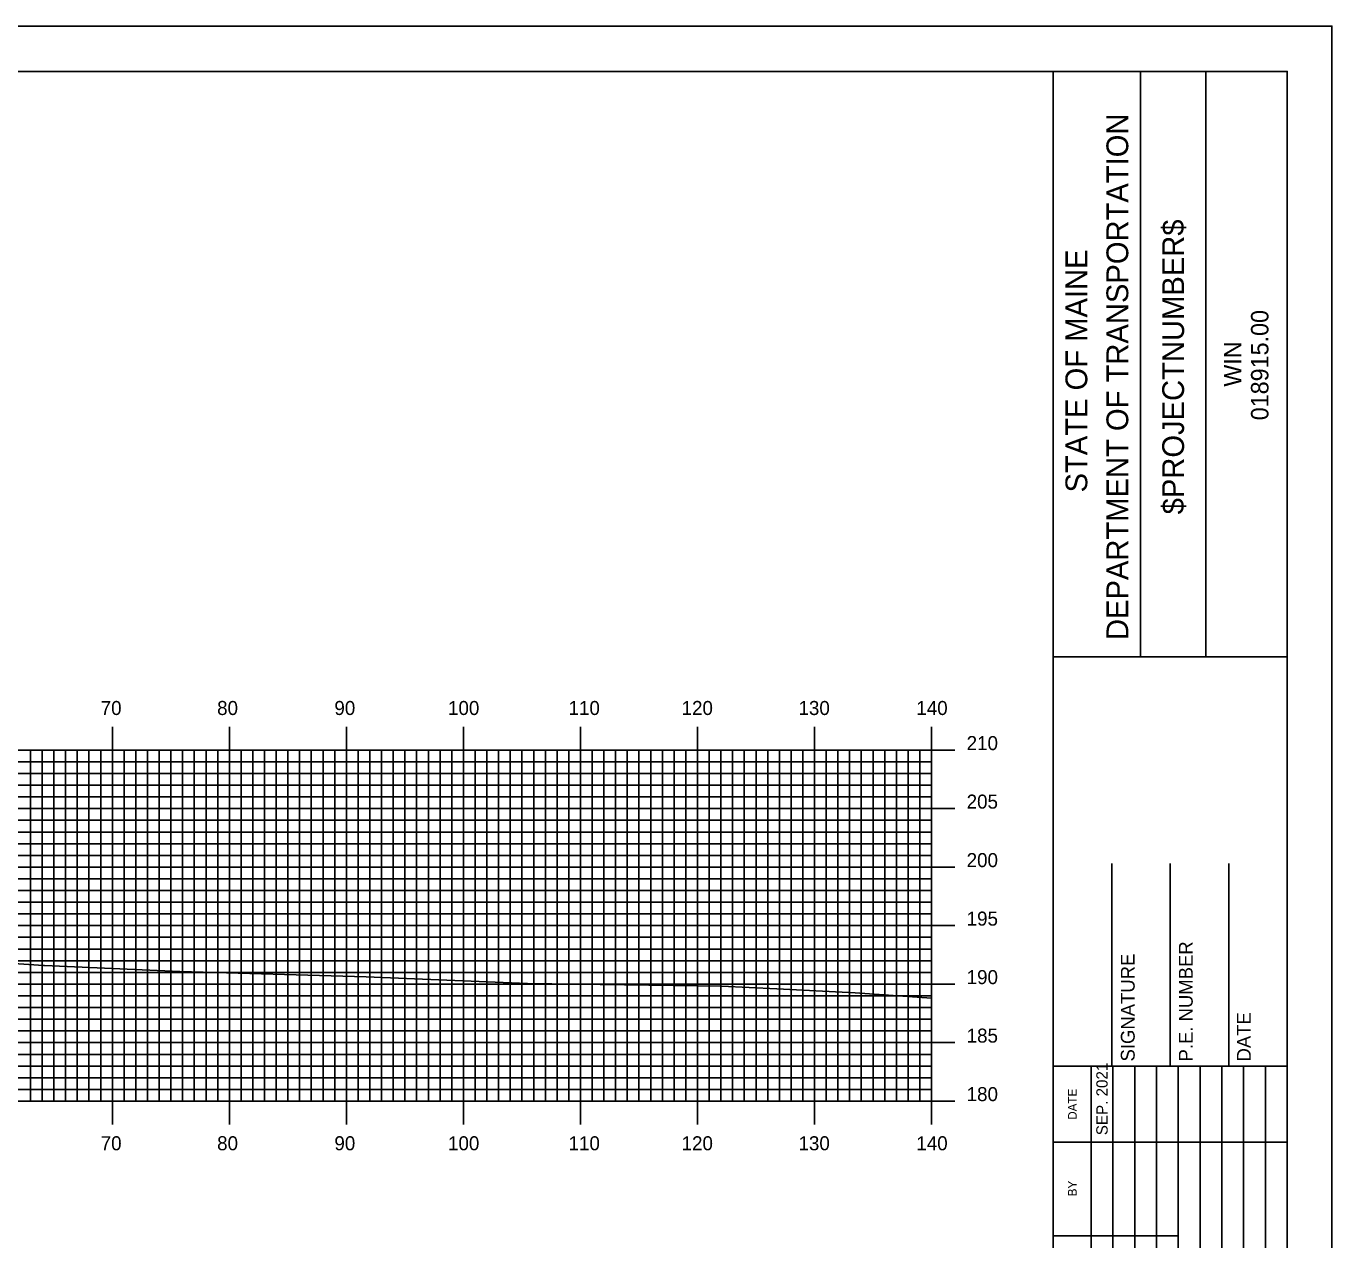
# Model space of a CAD drawing. Extents: x 1807045 to 1807388, y 442591 to 442811.
# Drawn here: x 1807273.4 to 1807385, y 442706.8 to 442810.5 of the extents above; entities that cross this region are included whole.
import ezdxf

# ---------------------------------------------------------------- set-up
doc = ezdxf.new("R2010")
doc.units = 0
for name, color, linetype in [('BORDER', 7, 'Continuous'), ('H_V ANNOTATION', 7, 'Continuous'), ('MAJOR', 7, 'Continuous'), ('MINOR', 7, 'Continuous'), ('PLOT BOUNDARY', 7, 'Continuous'), ('S_Roadway_Centerline', 7, 'Continuous')]:
    doc.layers.add(name, color=color, linetype=linetype)

msp = doc.modelspace()

# ---------------------------------------------------------------- linework, layer by layer
at = {"layer": 'BORDER'}
for p, q in [((1807361.16, 442596.67), (1807361.16, 442806.67)), ((1807368.62, 442756.66), (1807368.62, 442806.66)), ((1807374.21, 442756.66), (1807374.21, 442806.66)), ((1807361.16, 442756.65), (1807381.16, 442756.65)), ((1807366.16, 442721.67), (1807366.16, 442738.97)), ((1807371.16, 442721.67), (1807371.16, 442738.97)), ((1807376.16, 442721.67), (1807376.16, 442738.97)), ((1807361.16, 442721.67), (1807381.16, 442721.67))]:
    msp.add_line(p, q, dxfattribs=at)
msp.add_lwpolyline([(1807061.16, 442596.67), (1807381.16, 442596.67), (1807381.16, 442806.67), (1807061.16, 442806.67)], close=True, dxfattribs=at)
for points in [[(1807364.39, 442715.17), (1807364.39, 442721.67)], [(1807366.25, 442686.68), (1807366.25, 442721.67)], [(1807368.12, 442721.67), (1807368.12, 442686.68)], [(1807369.98, 442686.68), (1807369.98, 442721.67)], [(1807371.84, 442686.68), (1807371.84, 442721.67)], [(1807373.71, 442686.68), (1807373.71, 442721.67)], [(1807375.57, 442686.68), (1807375.57, 442721.67)], [(1807377.43, 442686.68), (1807377.43, 442721.67)], [(1807379.3, 442686.68), (1807379.3, 442721.67)], [(1807364.39, 442686.68), (1807364.39, 442720.26)], [(1807361.16, 442715.17), (1807381.16, 442715.17)], [(1807361.16, 442707.17), (1807364.39, 442707.17)], [(1807364.39, 442707.17), (1807371.84, 442707.17)]]:
    msp.add_lwpolyline(points, dxfattribs=at)
at = {"layer": 'MAJOR'}
for p, q in [((1807280.76, 442750.67), (1807280.76, 442748.67)), ((1807290.76, 442750.67), (1807290.76, 442748.67)), ((1807300.76, 442750.67), (1807300.76, 442748.67)), ((1807310.76, 442750.67), (1807310.76, 442748.67)), ((1807320.76, 442750.67), (1807320.76, 442748.67)), ((1807330.76, 442750.67), (1807330.76, 442748.67)), ((1807340.76, 442750.67), (1807340.76, 442748.67)), ((1807350.76, 442750.67), (1807350.76, 442748.67)), ((1807070.76, 442748.67), (1807350.76, 442748.67)), ((1807070.76, 442748.67), (1807350.76, 442748.67)), ((1807280.76, 442718.67), (1807280.76, 442748.67)), ((1807290.76, 442718.67), (1807290.76, 442748.67)), ((1807300.76, 442718.67), (1807300.76, 442748.67)), ((1807310.76, 442718.67), (1807310.76, 442748.67)), ((1807320.76, 442718.67), (1807320.76, 442748.67)), ((1807330.76, 442718.67), (1807330.76, 442748.67)), ((1807340.76, 442718.67), (1807340.76, 442748.67)), ((1807352.76, 442748.67), (1807348.75, 442748.67)), ((1807350.76, 442718.67), (1807350.76, 442748.67)), ((1807350.76, 442718.67), (1807350.76, 442748.67)), ((1807070.76, 442743.67), (1807350.76, 442743.67)), ((1807352.76, 442743.67), (1807348.75, 442743.67)), ((1807070.76, 442738.67), (1807350.76, 442738.67)), ((1807352.76, 442738.67), (1807348.75, 442738.67)), ((1807070.76, 442733.67), (1807350.76, 442733.67)), ((1807352.76, 442733.67), (1807348.75, 442733.67)), ((1807070.76, 442728.67), (1807350.76, 442728.67)), ((1807352.76, 442728.67), (1807348.75, 442728.67)), ((1807070.76, 442723.67), (1807350.76, 442723.67)), ((1807352.76, 442723.67), (1807348.75, 442723.67)), ((1807070.76, 442718.67), (1807350.76, 442718.67)), ((1807070.76, 442718.67), (1807350.76, 442718.67)), ((1807280.76, 442716.66), (1807280.76, 442718.67)), ((1807290.76, 442716.66), (1807290.76, 442718.67)), ((1807300.76, 442716.66), (1807300.76, 442718.67)), ((1807310.76, 442716.66), (1807310.76, 442718.67)), ((1807320.76, 442716.66), (1807320.76, 442718.67)), ((1807330.76, 442716.66), (1807330.76, 442718.67)), ((1807340.76, 442716.66), (1807340.76, 442718.67)), ((1807352.76, 442718.67), (1807348.75, 442718.67)), ((1807350.76, 442716.66), (1807350.76, 442718.67))]:
    msp.add_line(p, q, dxfattribs=at)
at = {"layer": 'MINOR'}
for p, q in [((1807273.76, 442718.67), (1807273.76, 442748.67)), ((1807274.76, 442718.67), (1807274.76, 442748.67)), ((1807275.76, 442718.67), (1807275.76, 442748.67)), ((1807276.76, 442718.67), (1807276.76, 442748.67)), ((1807277.76, 442718.67), (1807277.76, 442748.67)), ((1807278.76, 442718.67), (1807278.76, 442748.67)), ((1807279.76, 442718.67), (1807279.76, 442748.67)), ((1807281.76, 442718.67), (1807281.76, 442748.67)), ((1807282.76, 442718.67), (1807282.76, 442748.67)), ((1807283.76, 442718.67), (1807283.76, 442748.67)), ((1807284.76, 442718.67), (1807284.76, 442748.67)), ((1807285.76, 442718.67), (1807285.76, 442748.67)), ((1807286.76, 442718.67), (1807286.76, 442748.67)), ((1807287.76, 442718.67), (1807287.76, 442748.67)), ((1807288.76, 442718.67), (1807288.76, 442748.67)), ((1807289.76, 442718.67), (1807289.76, 442748.67)), ((1807291.76, 442718.67), (1807291.76, 442748.67)), ((1807292.76, 442718.67), (1807292.76, 442748.67)), ((1807293.76, 442718.67), (1807293.76, 442748.67)), ((1807294.76, 442718.67), (1807294.76, 442748.67)), ((1807295.76, 442718.67), (1807295.76, 442748.67)), ((1807296.76, 442718.67), (1807296.76, 442748.67)), ((1807297.76, 442718.67), (1807297.76, 442748.67)), ((1807298.76, 442718.67), (1807298.76, 442748.67)), ((1807299.76, 442718.67), (1807299.76, 442748.67)), ((1807301.76, 442718.67), (1807301.76, 442748.67)), ((1807302.76, 442718.67), (1807302.76, 442748.67)), ((1807303.76, 442718.67), (1807303.76, 442748.67)), ((1807304.76, 442718.67), (1807304.76, 442748.67)), ((1807305.76, 442718.67), (1807305.76, 442748.67)), ((1807306.76, 442718.67), (1807306.76, 442748.67)), ((1807307.76, 442718.67), (1807307.76, 442748.67)), ((1807308.76, 442718.67), (1807308.76, 442748.67)), ((1807309.76, 442718.67), (1807309.76, 442748.67)), ((1807311.76, 442718.67), (1807311.76, 442748.67)), ((1807312.76, 442718.67), (1807312.76, 442748.67)), ((1807313.76, 442718.67), (1807313.76, 442748.67)), ((1807314.76, 442718.67), (1807314.76, 442748.67)), ((1807315.76, 442718.67), (1807315.76, 442748.67)), ((1807316.76, 442718.67), (1807316.76, 442748.67)), ((1807317.76, 442718.67), (1807317.76, 442748.67)), ((1807318.76, 442718.67), (1807318.76, 442748.67)), ((1807319.76, 442718.67), (1807319.76, 442748.67)), ((1807321.76, 442718.67), (1807321.76, 442748.67)), ((1807322.76, 442718.67), (1807322.76, 442748.67)), ((1807323.76, 442718.67), (1807323.76, 442748.67)), ((1807324.76, 442718.67), (1807324.76, 442748.67)), ((1807325.76, 442718.67), (1807325.76, 442748.67)), ((1807326.76, 442718.67), (1807326.76, 442748.67)), ((1807327.76, 442718.67), (1807327.76, 442748.67)), ((1807328.76, 442718.67), (1807328.76, 442748.67)), ((1807329.76, 442718.67), (1807329.76, 442748.67)), ((1807331.76, 442718.67), (1807331.76, 442748.67)), ((1807332.76, 442718.67), (1807332.76, 442748.67)), ((1807333.76, 442718.67), (1807333.76, 442748.67)), ((1807334.76, 442718.67), (1807334.76, 442748.67)), ((1807335.76, 442718.67), (1807335.76, 442748.67)), ((1807336.76, 442718.67), (1807336.76, 442748.67)), ((1807337.76, 442718.67), (1807337.76, 442748.67)), ((1807338.76, 442718.67), (1807338.76, 442748.67)), ((1807339.76, 442718.67), (1807339.76, 442748.67)), ((1807341.76, 442718.67), (1807341.76, 442748.67)), ((1807342.76, 442718.67), (1807342.76, 442748.67)), ((1807343.76, 442718.67), (1807343.76, 442748.67)), ((1807344.76, 442718.67), (1807344.76, 442748.67)), ((1807345.76, 442718.67), (1807345.76, 442748.67)), ((1807346.76, 442718.67), (1807346.76, 442748.67)), ((1807347.76, 442718.67), (1807347.76, 442748.67)), ((1807348.76, 442718.67), (1807348.76, 442748.67)), ((1807349.76, 442718.67), (1807349.76, 442748.67)), ((1807070.76, 442747.67), (1807350.76, 442747.67)), ((1807070.76, 442746.67), (1807350.76, 442746.67)), ((1807350.76, 442747.67), (1807348.75, 442747.67)), ((1807350.76, 442746.67), (1807348.75, 442746.67)), ((1807070.76, 442745.67), (1807350.76, 442745.67)), ((1807350.76, 442745.67), (1807348.75, 442745.67)), ((1807070.76, 442744.67), (1807350.76, 442744.67)), ((1807350.76, 442744.67), (1807348.75, 442744.67)), ((1807070.76, 442742.67), (1807350.76, 442742.67)), ((1807350.76, 442742.67), (1807348.75, 442742.67)), ((1807070.76, 442741.67), (1807350.76, 442741.67)), ((1807350.76, 442741.67), (1807348.75, 442741.67)), ((1807070.76, 442740.67), (1807350.76, 442740.67)), ((1807350.76, 442740.67), (1807348.75, 442740.67)), ((1807070.76, 442739.67), (1807350.76, 442739.67)), ((1807350.76, 442739.67), (1807348.75, 442739.67)), ((1807070.76, 442737.67), (1807350.76, 442737.67)), ((1807070.76, 442736.67), (1807350.76, 442736.67)), ((1807350.76, 442737.67), (1807348.75, 442737.67)), ((1807350.76, 442736.67), (1807348.75, 442736.67)), ((1807070.76, 442735.67), (1807350.76, 442735.67)), ((1807350.76, 442735.67), (1807348.75, 442735.67)), ((1807070.76, 442734.67), (1807350.76, 442734.67)), ((1807350.76, 442734.67), (1807348.75, 442734.67)), ((1807070.76, 442732.67), (1807350.76, 442732.67)), ((1807350.76, 442732.67), (1807348.75, 442732.67)), ((1807070.76, 442731.67), (1807350.76, 442731.67)), ((1807350.76, 442731.67), (1807348.75, 442731.67)), ((1807070.76, 442730.67), (1807350.76, 442730.67)), ((1807350.76, 442730.67), (1807348.75, 442730.67)), ((1807070.76, 442729.67), (1807350.76, 442729.67)), ((1807350.76, 442729.67), (1807348.75, 442729.67)), ((1807070.76, 442727.67), (1807350.76, 442727.67)), ((1807070.76, 442726.67), (1807350.76, 442726.67)), ((1807350.76, 442727.67), (1807348.75, 442727.67)), ((1807350.76, 442726.67), (1807348.75, 442726.67)), ((1807070.76, 442725.67), (1807350.76, 442725.67)), ((1807350.76, 442725.67), (1807348.75, 442725.67)), ((1807070.76, 442724.67), (1807350.76, 442724.67)), ((1807350.76, 442724.67), (1807348.75, 442724.67)), ((1807070.76, 442722.67), (1807350.76, 442722.67)), ((1807350.76, 442722.67), (1807348.75, 442722.67)), ((1807070.76, 442721.67), (1807350.76, 442721.67)), ((1807350.76, 442721.67), (1807348.75, 442721.67)), ((1807070.76, 442720.67), (1807350.76, 442720.67)), ((1807350.76, 442720.67), (1807348.75, 442720.67)), ((1807070.76, 442719.67), (1807350.76, 442719.67)), ((1807350.76, 442719.67), (1807348.75, 442719.67))]:
    msp.add_line(p, q, dxfattribs=at)
at = {"layer": 'PLOT BOUNDARY'}
msp.add_lwpolyline([(1807044.97, 442590.55), (1807384.97, 442590.55), (1807384.97, 442810.55), (1807044.97, 442810.55)], close=True, dxfattribs=at)
at = {"layer": 'S_Roadway_Centerline'}
msp.add_lwpolyline([(1807263.1, 442731.07), (1807274.86, 442730.25), (1807274.91, 442730.25), (1807274.96, 442730.25), (1807286.53, 442729.75), (1807302.44, 442729.3), (1807316.24, 442728.73), (1807332.81, 442728.5), (1807337.55, 442728.26), (1807344.24, 442727.93), (1807350.76, 442727.48)], dxfattribs=at)

# ---------------------------------------------------------------- texts
at = {"layer": 'BORDER'}
for s, height, p in [('DEPARTMENT OF TRANSPORTATION', 1.8635, (1807367.57, 442758.08)), ('$PROJECTNUMBER$', 1.8635, (1807372.34, 442768.82)), ('STATE OF MAINE', 1.8635, (1807364.07, 442770.69)), ('018915.00', 1.491, (1807379.55, 442776.86)), ('WIN', 1.491, (1807377.23, 442779.73)), ('P.E. NUMBER', 1.1811, (1807373.08, 442722.06)), ('SIGNATURE', 1.181, (1807368.12, 442722.06)), ('DATE', 1.181, (1807378.04, 442722.06)), ('SEP. 2021', 0.969, (1807365.81, 442715.76)), ('DATE', 0.743, (1807363.17, 442717.08)), ('BY', 0.743, (1807363.17, 442710.54))]:
    msp.add_text(s, height=height, rotation=90, dxfattribs=at).set_placement(p)
at = {"layer": 'H_V ANNOTATION'}
for s, p in [('70', (1807279.76, 442751.67)), ('80', (1807289.71, 442751.67)), ('90', (1807299.73, 442751.67)), ('100', (1807309.44, 442751.67)), ('110', (1807319.74, 442751.67)), ('120', (1807329.4, 442751.67)), ('130', (1807339.39, 442751.67)), ('140', (1807349.46, 442751.67)), ('210', (1807353.76, 442748.67)), ('205', (1807353.76, 442743.67)), ('200', (1807353.76, 442738.67)), ('195', (1807353.76, 442733.67)), ('190', (1807353.76, 442728.67)), ('185', (1807353.76, 442723.67)), ('180', (1807353.76, 442718.67)), ('70', (1807279.76, 442714.47)), ('80', (1807289.71, 442714.47)), ('90', (1807299.73, 442714.47)), ('100', (1807309.44, 442714.47)), ('110', (1807319.74, 442714.47)), ('120', (1807329.4, 442714.47)), ('130', (1807339.39, 442714.47)), ('140', (1807349.46, 442714.47))]:
    msp.add_text(s, height=1.2, dxfattribs=at).set_placement(p)

doc.saveas('drawing.dxf')
